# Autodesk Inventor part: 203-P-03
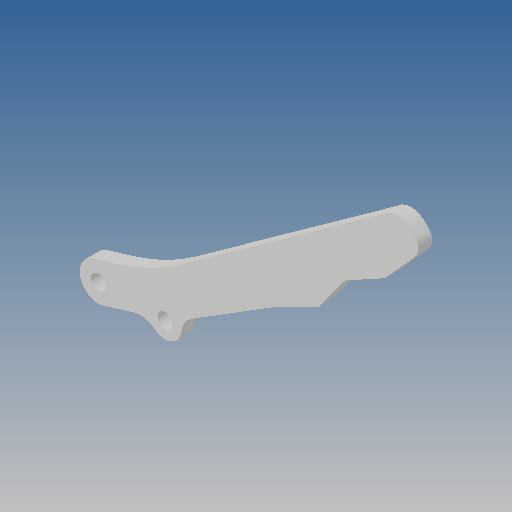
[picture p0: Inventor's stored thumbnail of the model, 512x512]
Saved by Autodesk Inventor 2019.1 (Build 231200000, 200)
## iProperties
Created: 2015-08
Part Number: 203-P-03
Material: Ogólny
Document SubType Name: Modeling
Designer: CADENGINEERING4
Density: 1 g/cm^3
Appearance: Domyślna
Author: CADENGINEERING4
Revision Number: ÈÎºÎ
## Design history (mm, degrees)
feature "Ô²½Ç1"
node "Bryła1"
